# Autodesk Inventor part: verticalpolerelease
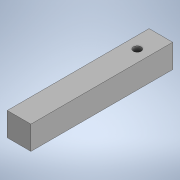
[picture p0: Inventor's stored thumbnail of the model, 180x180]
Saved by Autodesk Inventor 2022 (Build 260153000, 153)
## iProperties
Created: 2021-06
Part Number: verticalpolerelease
Material: Generic
Document SubType Name: Modeling
Designer: Chimms
Density: 1 g/cm^3
Appearance: Default
Author: Chimms
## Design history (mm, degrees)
sketch "Sketch1"
  geometry: L1 (0, 0)-(30, 0); L2 (30, 0)-(30, 30); L3 (30, 30)-(0, 30); L4 (0, 30)-(0, 0)
  constraints: 8 end point, 2 parallel, 1 horizontal, 1 perpendicular
  dimensions: "d0" = 30 distance of L3.end L2.end; "d1" = 30 distance of L2.end L1.end
extrude "Extrusion1" new body sketch "Sketch1" distance "d2" = 180; taper "d3" = 0 deg
sketch "Sketch2"
  geometry: L1 (30, 0)-(0, 0) reference; C1 r 5 at (15, -30)
  constraints: 1 centre point
  dimensions: "d5" = 10 diameter of C1
extrude "Extrusion2" cut sketch "Sketch2" extent not by distance; stored distance "d6" = 0; taper "d7" = 0 deg
body "Solid1"
